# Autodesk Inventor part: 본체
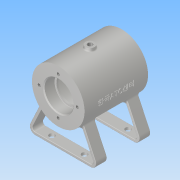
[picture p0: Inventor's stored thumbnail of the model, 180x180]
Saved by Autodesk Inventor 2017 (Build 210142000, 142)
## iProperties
Part Number: 본체
Material: 알루미늄 6061
Document SubType Name: Modeling
Designer: Administrator
Density: 2.7 g/cm^3
Appearance: 알루미늄 - 평지
Mass: 308.872 g
Surface Area: 350.956 cm^2
Volume: 114.397 cm^3
Author: Administrator
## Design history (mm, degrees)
sketch "스케치3"
  geometry: C1 r 29 at (0, 0); 1 further point
  constraints: 1 centre point, 1 coincident
  dimensions: "d0" = 58 diameter of C1
extrude "돌출1" new body sketch "스케치3" stored distance "d1" = 70; taper "d2" = 0 deg
node "작업 평면1"
sketch "스케치4"
  geometry: L1 (-22.743, -17.993)-(-40, -55); L2 (-40, -55)-(40, -55); L3 (40, -55)-(22.743, -17.993); L4 (0, 0)-(0, -55); A1 r 29 centre (0, 0) between (-22.743, -17.993) and (22.743, -17.993) reference; A2 r 29 centre (0, 0) between (-22.743, -17.993) and (22.743, -17.993) reference; A3 r 29 centre (0, 0) between (-22.743, -17.993) and (22.743, -17.993); 1 further point
  constraints: 8 end point, 6 point on circle, 1 centre point, 1 horizontal, 1 midpoint, 1 perpendicular, 1 other
  dimensions: "d4" = 55 distance from line of L2 point (0, 0); "d5" = 65 deg angle of L2 L1; "d6" = 80 distance of L1.end L2.end
extrude "돌출2" join sketch "스케치4" distance "d7" = 12; taper "d8" = 0 deg
sketch "스케치5"
  geometry: L1 (-22.743, -17.993)-(-40, -55) reference; L2 (-40, -55)-(40, -55) reference; L3 (40, -55)-(22.743, -17.993) reference; L4 (20.574, -20.438)-(35.291, -52); L5 (35.291, -52)-(-35.291, -52); L6 (-35.291, -52)-(-20.574, -20.438); A1 r 29 centre (0, 0) between (-22.743, -17.993) and (22.743, -17.993) reference; A2 r 32 centre (0, 0) between (-21.916, -23.317) and (21.916, -23.317); 1 further point
  constraints: 6 end point, 4 point on circle, 2 point on line, 1 centre point
  dimensions: "d9" = 3 distance between parallel lines of L3 L4; "d10" = 3 distance between parallel lines of L1 L6; "d11" = 3 distance between parallel lines of L2 L5
extrude "돌출3" cut sketch "스케치5" distance "d12" = 12; taper "d13" = 0 deg
node "작업 평면2"
sketch "스케치6"
  geometry: C1 r 5 at (0, 0); 1 further point
  constraints: 1 centre point, 1 coincident
  dimensions: "d15" = 10 diameter of C1
extrude "돌출4" join sketch "스케치6" stored distance "d16" = 12; taper "d17" = 0 deg
sketch "스케치7"
  geometry: C1 r 16 at (0, 0); 1 further point
  constraints: 1 centre point, 1 coincident
  dimensions: "d18" = 32 diameter of C1
extrude "돌출5" cut sketch "스케치7" distance "d19" = 12; taper "d20" = 0 deg
sketch "스케치8"
  geometry: C1 r 16 at (0, 0); 1 further point
  constraints: 1 centre point, 1 coincident
  dimensions: "d21" = 32 diameter of C1
extrude "돌출6" cut sketch "스케치8" distance "d22" = 12; taper "d23" = 0 deg
sketch "스케치9"
  geometry: C1 r 14 at (0, 0); 1 further point
  constraints: 1 centre point, 1 coincident
  dimensions: "d24" = 28 diameter of C1
extrude "돌출7" cut sketch "스케치9" distance "d25" = 2; taper "d26" = 0 deg
sketch "스케치10"
  geometry: C1 r 14 at (0, 0); 1 further point
  constraints: 1 centre point, 1 coincident
  dimensions: "d27" = 28 diameter of C1
extrude "돌출8" cut sketch "스케치10" distance "d28" = 2; taper "d29" = 0 deg
sketch "스케치11"
  geometry: C1 r 21 at (0, 0); 1 further point
  constraints: 1 centre point, 1 coincident
  dimensions: "d30" = 42 diameter of C1
extrude "돌출9" cut sketch "스케치11" distance "d31" = 42; taper "d32" = 0 deg
sketch "스케치13" dims "d33" = 42
  geometry: 3 further points
  constraints: 2 vertical alignment, 1 coincident, 2 other
hole "구멍1" sketch "스케치13" at (0, 21) diameter "d34" = 3.242; stored, may be unused: countersink angle "d38" = 90 deg, drill point angle "d40" = 118 deg; dims "d35" = 8, "d36" = 4, "d37" = 2, "d39" = 10
sketch "스케치15"
  geometry: C1 r 1.5 at (0, 0); 1 further point
  constraints: 1 centre point, 1 coincident
  dimensions: "d51" = 3 diameter of C1
extrude "돌출10" cut sketch "스케치15" distance "d52" = 17.5; taper "d53" = 0 deg
sketch "스케치16"
  geometry: 1 further point
hole "구멍3" sketch "스케치16" at (0, 0) diameter "d54" = 5.188; stored, may be unused: countersink angle "d58" = 90 deg, drill point angle "d60" = 118 deg; dims "d55" = 6, "d56" = 4, "d57" = 2, "d59" = 8
node "작업 평면7"
  node "작업 평면6"
sketch "스케치19"
  geometry: C1 r 6 at (0, 0); 1 further point
  constraints: 1 centre point, 1 coincident
  dimensions: "d67" = 12 diameter of C1
extrude "돌출11" join sketch "스케치19" stored distance "d68" = 17.5; taper "d69" = 0 deg
sketch "스케치20"
  geometry: 1 further point
hole "구멍4" sketch "스케치20" at (0, 0) diameter "d70" = 5.188; stored, may be unused: countersink angle "d74" = 90 deg, drill point angle "d76" = 118 deg; dims "d71" = 6, "d72" = 4, "d73" = 2, "d75" = 13.5
sketch "스케치21"
  geometry: L1 (70.582, 48)-(70.582, 60) reference; L2 (0, 60)-(70.582, 60) reference; L3 (-3.31, 60)-(0, 60) reference; L4 (-3.31, 48)-(-3.31, 60) reference; L5 (0, 48)-(-3.31, 48) reference; L6 (0, 60)-(0, 48) reference; L7 (70.582, 48)-(0, 48) reference; L8 (73.892, 48)-(70.582, 48) reference; L9 (73.892, 60)-(73.892, 48) reference; L10 (70.582, 60)-(73.892, 60) reference; L11 (70.582, 0)-(70.582, 12) reference; L12 (0, 12)-(70.582, 12) reference; L13 (-3.31, 12)-(0, 12) reference; L14 (-3.31, 0)-(-3.31, 12) reference; L15 (0, 0)-(-3.31, 0) reference; L16 (0, 12)-(0, 0) reference; L17 (70.582, 0)-(0, 0) reference; L18 (73.892, 0)-(70.582, 0) reference; L19 (73.892, 12)-(73.892, 0) reference; L20 (70.582, 12)-(73.892, 12) reference; L21 (-4.709, 0)-(75.291, 0) reference; L22 (35.291, 0)-(35.291, 60); C1 r 3 at (17.291, 6); C2 r 3 at (53.291, 6); 3 further points
  constraints: 2 centre point, 2 coincident, 2 end point, 2 midpoint, 1 horizontal alignment
  dimensions: "d79" = 18 distance from line of L22 point (17.291, 6); "d80" = 18 horizontal distance of point (53.291, 6) point (35.291, 30); "d81" = 6 distance from line of L21 point (17.291, 6); "d82" = 6 diameter of C1; "d83" = 6 diameter of C2
extrude "돌출12" cut sketch "스케치21" stored distance "d84" = 17.5; taper "d85" = 0 deg
fillet "모깎기2" dims "d90" = 6
fillet "모깎기3" dims "d91" = 3
fillet "모깎기4" dims "d95" = 0.3
fillet "모깎기5" dims "d96" = 3
fillet "모깎기10" dims "d101" = 1
node "작업 평면8"
sketch "스케치22" dims "d0" = 58
  geometry: L1 (29, 35)-(-29, 35) reference; L2 (29, -35)-(29, 35) reference; 2 further points
  constraints: 1 other
  dimensions: "d103" = 35 distance from line of L1 point (0, 0); "d104" = 29 distance from line of L2 point (0, 0)
feature "엠보싱1" sketch "스케치22" dims "d0" = 58, "d105" = 0.5, "d106" = 0
fillet "모깎기11" dims "d107" = 0.5
chamfer "모따기3" distance "d109" = 1; stored, may be unused: second distance "d110" = 2, angle "d111" = 45 deg
fillet "모깎기13" dims "d112" = 3
node "솔리드1"
mirror "미러1"
pattern_circular "원형 패턴1" dims angle "d42" = 360 deg
mirror "미러2"
mirror "미러3"
node "투영된 루프1"
node "절단 모서리 투영1"
node "절단 모서리 투영4"
other parameters: "d3" = -5, "d14" = 32, "d65" = 250 deg, "d66" = 32, "d102" = 64
